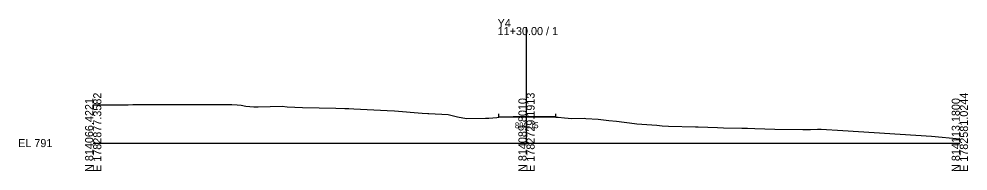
# Model space of a CAD drawing. Extents: x -26 to 3903, y -10 to 9562.
# Drawn here: x -25.7 to 302.8, y 2990.3 to 3043 of the extents above; entities that cross this region are included whole.
import ezdxf

# ---------------------------------------------------------------- set-up
doc = ezdxf.new("R2010")
doc.units = 0
for name, color, linetype in [('Exist Cross Section Cell', 7, 'Continuous'), ('Exist XS Center Line Elevation Label', 7, 'Continuous'), ('Exist XS Ground Line', 7, 'Continuous'), ('Prop XS EOT Tick Mark', 7, 'Continuous'), ('Prop XS Finish Grade Pavement', 7, 'Continuous')]:
    doc.layers.add(name, color=color, linetype=linetype)

msp = doc.modelspace()

# ---------------------------------------------------------------- linework, layer by layer
at = {"layer": 'Exist Cross Section Cell'}
for p, q in [((150, 3000), (150, 3040.24)), ((0, 3000), (150, 3000)), ((150, 3000), (300, 3000))]:
    msp.add_line(p, q, dxfattribs=at)
at = {"layer": 'Exist XS Ground Line'}
for p, q in [((0, 3013.21), (4.81, 3013.23)), ((4.81, 3013.23), (9.4, 3013.28)), ((9.4, 3013.28), (12.14, 3013.31)), ((12.14, 3013.31), (13.73, 3013.34)), ((13.73, 3013.34), (14.21, 3013.33)), ((14.21, 3013.33), (22.75, 3013.41)), ((22.75, 3013.41), (29.15, 3013.4)), ((29.15, 3013.4), (31.14, 3013.4)), ((31.14, 3013.4), (32.14, 3013.4)), ((32.14, 3013.4), (37.21, 3013.39)), ((37.21, 3013.39), (39.63, 3013.38)), ((39.63, 3013.38), (42.63, 3013.37)), ((42.63, 3013.37), (45.21, 3013.37)), ((45.21, 3013.37), (46.16, 3013.37)), ((46.16, 3013.37), (47.95, 3013.39)), ((47.95, 3013.39), (49.81, 3013.27)), ((49.81, 3013.27), (51.25, 3013.1)), ((51.25, 3013.1), (52.79, 3012.82)), ((52.79, 3012.82), (55.6, 3012.62)), ((57.1, 3012.59), (61.3, 3012.68)), ((61.3, 3012.68), (65.45, 3012.75)), ((65.45, 3012.75), (67.1, 3012.59)), ((55.6, 3012.62), (57.1, 3012.59)), ((67.1, 3012.59), (72.43, 3012.37)), ((72.43, 3012.37), (84.04, 3012.07)), ((84.04, 3012.07), (87.12, 3012)), ((87.12, 3012), (88.5, 3011.95)), ((88.5, 3011.95), (90.28, 3011.9)), ((90.28, 3011.9), (101.81, 3011.35)), ((101.81, 3011.35), (104.32, 3011.21)), ((104.32, 3011.21), (113.84, 3010.42)), ((113.84, 3010.42), (115.82, 3010.26)), ((115.82, 3010.26), (116.19, 3010.25)), ((116.19, 3010.25), (122.92, 3009.91)), ((122.92, 3009.91), (126.12, 3009.11)), ((126.12, 3009.11), (129.27, 3008.58)), ((129.27, 3008.58), (135.83, 3008.66)), ((135.83, 3008.66), (136.99, 3008.66)), ((136.99, 3008.66), (139.7, 3008.82)), ((139.7, 3008.82), (140.38, 3009.04)), ((140.38, 3009.04), (150.22, 3009.16)), ((150.22, 3009.16), (160.14, 3009.04)), ((160.14, 3009.04), (160.94, 3008.97)), ((160.94, 3008.97), (163.1, 3008.72)), ((163.1, 3008.72), (165.72, 3008.52)), ((165.72, 3008.52), (170.1, 3008.59)), ((170.1, 3008.59), (170.59, 3008.58)), ((170.59, 3008.58), (174.85, 3008.29)), ((174.85, 3008.29), (178.5, 3007.87)), ((178.5, 3007.87), (181.12, 3007.59)), ((181.12, 3007.59), (187.33, 3006.8)), ((187.33, 3006.8), (188.18, 3006.73)), ((188.18, 3006.73), (195.06, 3006.18)), ((195.06, 3006.18), (196.94, 3006.04)), ((196.94, 3006.04), (199.12, 3005.92)), ((199.12, 3005.92), (208.54, 3005.69)), ((208.54, 3005.69), (209.46, 3005.67)), ((209.46, 3005.67), (216.1, 3005.41)), ((216.1, 3005.41), (218.21, 3005.3)), ((218.21, 3005.3), (224.49, 3005.15)), ((224.49, 3005.15), (226.51, 3005.13)), ((226.51, 3005.13), (229.02, 3005.08)), ((229.02, 3005.08), (235.97, 3004.81)), ((235.97, 3004.81), (245.7, 3004.69)), ((245.7, 3004.69), (247.41, 3004.69)), ((247.41, 3004.69), (248.34, 3004.71)), ((248.34, 3004.71), (250.73, 3004.8)), ((250.73, 3004.8), (251.5, 3004.8)), ((251.5, 3004.8), (251.97, 3004.79)), ((251.97, 3004.79), (259.46, 3004.37)), ((259.46, 3004.37), (290.25, 3002.41)), ((290.25, 3002.41), (300, 3001.48))]:
    msp.add_line(p, q, dxfattribs=at)
at = {"layer": 'Prop XS EOT Tick Mark'}
for p, q in [((140.38, 3009.16), (140.38, 3010.16)), ((160.14, 3009.17), (160.14, 3010.17))]:
    msp.add_line(p, q, dxfattribs=at)
at = {"layer": 'Prop XS Finish Grade Pavement'}
for p, q in [((140.38, 3009.16), (150.22, 3009.28)), ((150.22, 3009.28), (160.14, 3009.17))]:
    msp.add_line(p, q, dxfattribs=at)

# ---------------------------------------------------------------- texts
at = {"layer": 'Exist Cross Section Cell'}
for s, p in [('Y4', (140, 3040.24)), ('11+30.00 / 1', (140, 3037.44)), ('EL 791', (-26, 2998.6))]:
    msp.add_text(s, height=2.8, dxfattribs=at).set_placement(p)
for s, p in [('E 1782877.3582', (2.8, 2990)), ('E 1782729.1913', (152.8, 2990)), ('E 1782581.0244', (302.8, 2990)), ('N 814066.4221', (0, 2990)), ('N 814089.8010', (150, 2990)), ('N 814113.1800', (300, 2990))]:
    msp.add_text(s, height=2.8, rotation=90, dxfattribs=at).set_placement(p)
at = {"layer": 'Exist XS Center Line Elevation Label'}
msp.add_text('800.15', height=2, dxfattribs=at).set_placement((145.98, 3005.15))

doc.saveas('drawing.dxf')
